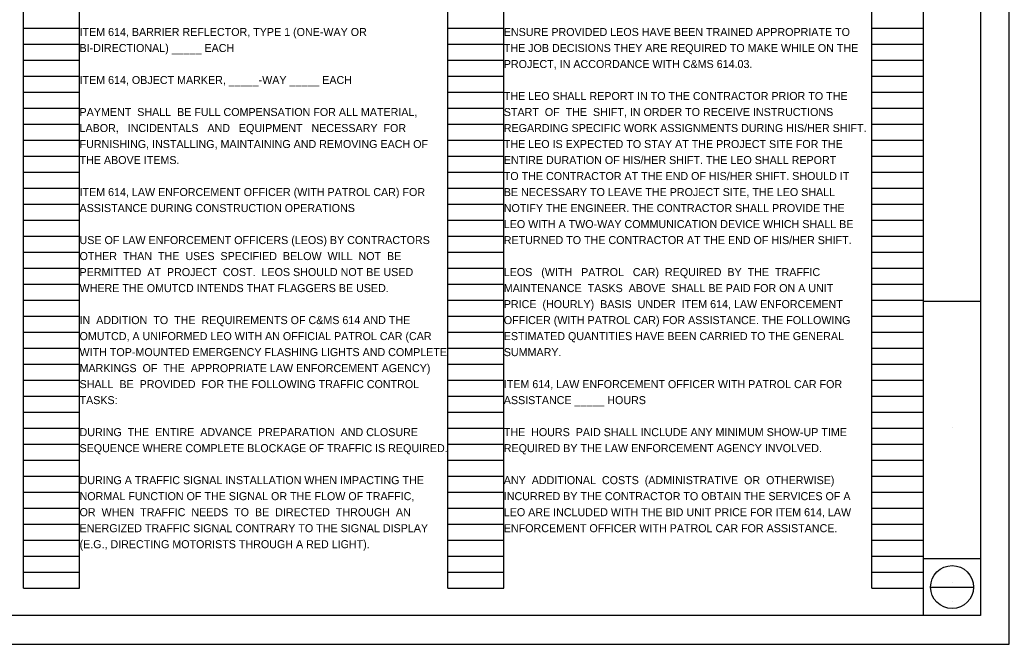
# Model space of a CAD drawing. Extents: x 0 to 34, y 0 to 22.
# Drawn here: x 16.69 to 34, y 0 to 10.92 of the extents above; entities that cross this region are included whole.
import ezdxf

# ---------------------------------------------------------------- set-up
doc = ezdxf.new("R2010")
doc.units = 0
for name, color, linetype in [('SH_Border', 7, 'Continuous'), ('SH_Cut_Line', 7, 'Continuous'), ('SH_Data', 7, 'Continuous'), ('SH_Text', 7, 'Continuous')]:
    doc.layers.add(name, color=color, linetype=linetype)

msp = doc.modelspace()

# ---------------------------------------------------------------- linework, layer by layer
at = {"layer": 'SH_Border'}
for p, q in [((32.5, 0.5), (32.5, 21.5)), ((32.5, 6), (33.5, 6)), ((32.5, 1.5), (33.5, 1.5))]:
    msp.add_line(p, q, dxfattribs=at)
msp.add_lwpolyline([(2, 21.5), (33.5, 21.5), (33.5, 0.5), (2, 0.5)], close=True, dxfattribs=at)
at = {"layer": 'SH_Cut_Line'}
msp.add_lwpolyline([(0, 0), (34, 0), (34, 22), (0, 22)], close=True, dxfattribs=at)
at = {"layer": 'SH_Data'}
for p, q in [((16.76, 0.98), (16.76, 21.14)), ((17.74, 0.98), (17.74, 21.14)), ((24.18, 0.98), (24.18, 21.14)), ((25.16, 0.98), (25.16, 21.14)), ((31.6, 0.98), (31.6, 21.14)), ((32.5, 0.98), (32.5, 21.14)), ((16.76, 10.78), (17.74, 10.78)), ((24.18, 10.78), (25.16, 10.78)), ((31.6, 10.78), (32.5, 10.78)), ((16.76, 10.5), (17.74, 10.5)), ((24.18, 10.5), (25.16, 10.5)), ((31.6, 10.5), (32.5, 10.5)), ((16.76, 10.22), (17.74, 10.22)), ((24.18, 10.22), (25.16, 10.22)), ((31.6, 10.22), (32.5, 10.22)), ((16.76, 9.94), (17.74, 9.94)), ((24.18, 9.94), (25.16, 9.94)), ((31.6, 9.94), (32.5, 9.94)), ((16.76, 9.66), (17.74, 9.66)), ((24.18, 9.66), (25.16, 9.66)), ((31.6, 9.66), (32.5, 9.66)), ((16.76, 9.38), (17.74, 9.38)), ((24.18, 9.38), (25.16, 9.38)), ((31.6, 9.38), (32.5, 9.38)), ((16.76, 9.1), (17.74, 9.1)), ((24.18, 9.1), (25.16, 9.1)), ((31.6, 9.1), (32.5, 9.1)), ((16.76, 8.82), (17.74, 8.82)), ((24.18, 8.82), (25.16, 8.82)), ((31.6, 8.82), (32.5, 8.82)), ((16.76, 8.54), (17.74, 8.54)), ((24.18, 8.54), (25.16, 8.54)), ((31.6, 8.54), (32.5, 8.54)), ((16.76, 8.26), (17.74, 8.26)), ((24.18, 8.26), (25.16, 8.26)), ((31.6, 8.26), (32.5, 8.26)), ((16.76, 7.98), (17.74, 7.98)), ((24.18, 7.98), (25.16, 7.98)), ((31.6, 7.98), (32.5, 7.98)), ((16.76, 7.7), (17.74, 7.7)), ((24.18, 7.7), (25.16, 7.7)), ((31.6, 7.7), (32.5, 7.7)), ((16.76, 7.42), (17.74, 7.42)), ((24.18, 7.42), (25.16, 7.42)), ((31.6, 7.42), (32.5, 7.42)), ((16.76, 7.14), (17.74, 7.14)), ((24.18, 7.14), (25.16, 7.14)), ((31.6, 7.14), (32.5, 7.14)), ((16.76, 6.86), (17.74, 6.86)), ((24.18, 6.86), (25.16, 6.86)), ((31.6, 6.86), (32.5, 6.86)), ((16.76, 6.58), (17.74, 6.58)), ((24.18, 6.58), (25.16, 6.58)), ((31.6, 6.58), (32.5, 6.58)), ((16.76, 6.3), (17.74, 6.3)), ((24.18, 6.3), (25.16, 6.3)), ((31.6, 6.3), (32.5, 6.3)), ((16.76, 6.02), (17.74, 6.02)), ((24.18, 6.02), (25.16, 6.02)), ((31.6, 6.02), (32.5, 6.02)), ((16.76, 5.74), (17.74, 5.74)), ((24.18, 5.74), (25.16, 5.74)), ((31.6, 5.74), (32.5, 5.74)), ((16.76, 5.46), (17.74, 5.46)), ((24.18, 5.46), (25.16, 5.46)), ((31.6, 5.46), (32.5, 5.46)), ((16.76, 5.18), (17.74, 5.18)), ((24.18, 5.18), (25.16, 5.18)), ((31.6, 5.18), (32.5, 5.18)), ((16.76, 4.9), (17.74, 4.9)), ((24.18, 4.9), (25.16, 4.9)), ((31.6, 4.9), (32.5, 4.9)), ((16.76, 4.62), (17.74, 4.62)), ((24.18, 4.62), (25.16, 4.62)), ((31.6, 4.62), (32.5, 4.62)), ((16.76, 4.34), (17.74, 4.34)), ((24.18, 4.34), (25.16, 4.34)), ((31.6, 4.34), (32.5, 4.34)), ((16.76, 4.06), (17.74, 4.06)), ((24.18, 4.06), (25.16, 4.06)), ((31.6, 4.06), (32.5, 4.06)), ((16.76, 3.78), (17.74, 3.78)), ((24.18, 3.78), (25.16, 3.78)), ((31.6, 3.78), (32.5, 3.78)), ((33, 3.792), (33, 3.792)), ((16.76, 3.5), (17.74, 3.5)), ((24.18, 3.5), (25.16, 3.5)), ((31.6, 3.5), (32.5, 3.5)), ((16.76, 3.22), (17.74, 3.22)), ((24.18, 3.22), (25.16, 3.22)), ((31.6, 3.22), (32.5, 3.22)), ((16.76, 2.94), (17.74, 2.94)), ((24.18, 2.94), (25.16, 2.94)), ((31.6, 2.94), (32.5, 2.94)), ((16.76, 2.66), (17.74, 2.66)), ((24.18, 2.66), (25.16, 2.66)), ((31.6, 2.66), (32.5, 2.66)), ((16.76, 2.38), (17.74, 2.38)), ((24.18, 2.38), (25.16, 2.38)), ((31.6, 2.38), (32.5, 2.38)), ((16.76, 2.1), (17.74, 2.1)), ((24.18, 2.1), (25.16, 2.1)), ((31.6, 2.1), (32.5, 2.1)), ((16.76, 1.82), (17.74, 1.82)), ((24.18, 1.82), (25.16, 1.82)), ((31.6, 1.82), (32.5, 1.82)), ((16.76, 1.54), (17.74, 1.54)), ((24.18, 1.54), (25.16, 1.54)), ((31.6, 1.54), (32.5, 1.54)), ((16.76, 1.26), (17.74, 1.26)), ((24.18, 1.26), (25.16, 1.26)), ((31.6, 1.26), (32.5, 1.26)), ((33, 1.085), (33, 1.085)), ((16.76, 0.98), (17.74, 0.98)), ((24.18, 0.98), (25.16, 0.98)), ((31.6, 0.98), (32.5, 0.98)), ((32.625, 1), (33.375, 1)), ((33, 0.745), (33, 0.745))]:
    msp.add_line(p, q, dxfattribs=at)
msp.add_circle((33, 1), 0.375, dxfattribs=at)

# ---------------------------------------------------------------- texts
at = {"layer": 'SH_Text'}
for s, p in [('ITEM 614, BARRIER REFLECTOR, TYPE 1 (ONE-WAY OR', (17.74, 10.64)), ('ENSURE PROVIDED LEOS HAVE BEEN TRAINED APPROPRIATE TO', (25.16, 10.64)), ('BI-DIRECTIONAL) _____ EACH', (17.74, 10.36)), ('THE JOB DECISIONS THEY ARE REQUIRED TO MAKE WHILE ON THE', (25.16, 10.36)), ('PROJECT, IN ACCORDANCE WITH C&MS 614.03.', (25.16, 10.08)), ('ITEM 614, OBJECT MARKER, _____-WAY _____ EACH', (17.74, 9.8)), ('THE LEO SHALL REPORT IN TO THE CONTRACTOR PRIOR TO THE', (25.16, 9.52)), ('PAYMENT  SHALL  BE FULL COMPENSATION FOR ALL MATERIAL,', (17.74, 9.24)), ('START  OF  THE  SHIFT, IN ORDER TO RECEIVE INSTRUCTIONS', (25.16, 9.24)), ('LABOR,   INCIDENTALS   AND   EQUIPMENT   NECESSARY  FOR', (17.74, 8.96)), ('REGARDING SPECIFIC WORK ASSIGNMENTS DURING HIS/HER SHIFT.', (25.16, 8.96)), ('FURNISHING, INSTALLING, MAINTAINING AND REMOVING EACH OF', (17.74, 8.68)), ('THE LEO IS EXPECTED TO STAY AT THE PROJECT SITE FOR THE', (25.16, 8.68)), ('THE ABOVE ITEMS.', (17.74, 8.4)), ('ENTIRE DURATION OF HIS/HER SHIFT. THE LEO SHALL REPORT', (25.16, 8.4)), ('TO THE CONTRACTOR AT THE END OF HIS/HER SHIFT. SHOULD IT', (25.16, 8.12)), ('ITEM 614, LAW ENFORCEMENT OFFICER (WITH PATROL CAR) FOR', (17.74, 7.84)), ('BE NECESSARY TO LEAVE THE PROJECT SITE, THE LEO SHALL', (25.16, 7.84)), ('ASSISTANCE DURING CONSTRUCTION OPERATIONS', (17.74, 7.56)), ('NOTIFY THE ENGINEER. THE CONTRACTOR SHALL PROVIDE THE', (25.16, 7.56)), ('LEO WITH A TWO-WAY COMMUNICATION DEVICE WHICH SHALL BE', (25.16, 7.28)), ('USE OF LAW ENFORCEMENT OFFICERS (LEOS) BY CONTRACTORS', (17.74, 7)), ('RETURNED TO THE CONTRACTOR AT THE END OF HIS/HER SHIFT.', (25.16, 7)), ('OTHER  THAN  THE  USES  SPECIFIED  BELOW  WILL  NOT  BE', (17.74, 6.72)), ('PERMITTED  AT  PROJECT  COST.  LEOS SHOULD NOT BE USED', (17.74, 6.44)), ('LEOS   (WITH   PATROL   CAR)  REQUIRED  BY  THE  TRAFFIC', (25.16, 6.44)), ('WHERE THE OMUTCD INTENDS THAT FLAGGERS BE USED.', (17.74, 6.16)), ('MAINTENANCE  TASKS  ABOVE  SHALL BE PAID FOR ON A UNIT', (25.16, 6.16)), ('PRICE  (HOURLY)  BASIS  UNDER  ITEM 614, LAW ENFORCEMENT', (25.16, 5.88)), ('IN  ADDITION  TO  THE  REQUIREMENTS OF C&MS 614 AND THE', (17.74, 5.6)), ('OFFICER (WITH PATROL CAR) FOR ASSISTANCE. THE FOLLOWING', (25.16, 5.6)), ('OMUTCD, A UNIFORMED LEO WITH AN OFFICIAL PATROL CAR (CAR', (17.74, 5.32)), ('ESTIMATED QUANTITIES HAVE BEEN CARRIED TO THE GENERAL', (25.16, 5.32)), ('WITH TOP-MOUNTED EMERGENCY FLASHING LIGHTS AND COMPLETE', (17.74, 5.04)), ('SUMMARY.', (25.16, 5.04)), ('MARKINGS  OF  THE  APPROPRIATE LAW ENFORCEMENT AGENCY)', (17.74, 4.76)), ('SHALL  BE  PROVIDED  FOR THE FOLLOWING TRAFFIC CONTROL', (17.74, 4.48)), ('ITEM 614, LAW ENFORCEMENT OFFICER WITH PATROL CAR FOR', (25.16, 4.48)), ('TASKS:', (17.74, 4.2)), ('ASSISTANCE _____ HOURS', (25.16, 4.2)), ('DURING  THE  ENTIRE  ADVANCE  PREPARATION  AND CLOSURE', (17.74, 3.64)), ('THE  HOURS  PAID SHALL INCLUDE ANY MINIMUM SHOW-UP TIME', (25.16, 3.64)), ('SEQUENCE WHERE COMPLETE BLOCKAGE OF TRAFFIC IS REQUIRED.', (17.74, 3.36)), ('REQUIRED BY THE LAW ENFORCEMENT AGENCY INVOLVED.', (25.16, 3.36)), ('DURING A TRAFFIC SIGNAL INSTALLATION WHEN IMPACTING THE', (17.74, 2.8)), ('ANY  ADDITIONAL  COSTS  (ADMINISTRATIVE  OR  OTHERWISE)', (25.16, 2.8)), ('NORMAL FUNCTION OF THE SIGNAL OR THE FLOW OF TRAFFIC,', (17.74, 2.52)), ('INCURRED BY THE CONTRACTOR TO OBTAIN THE SERVICES OF A', (25.16, 2.52)), ('OR  WHEN  TRAFFIC  NEEDS  TO  BE  DIRECTED  THROUGH  AN', (17.74, 2.24)), ('LEO ARE INCLUDED WITH THE BID UNIT PRICE FOR ITEM 614, LAW', (25.16, 2.24)), ('ENERGIZED TRAFFIC SIGNAL CONTRARY TO THE SIGNAL DISPLAY', (17.74, 1.96)), ('ENFORCEMENT OFFICER WITH PATROL CAR FOR ASSISTANCE.', (25.16, 1.96)), ('(E.G., DIRECTING MOTORISTS THROUGH A RED LIGHT).', (17.74, 1.68))]:
    msp.add_text(s, height=0.14, dxfattribs=at).set_placement(p)

doc.saveas('drawing.dxf')
